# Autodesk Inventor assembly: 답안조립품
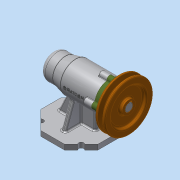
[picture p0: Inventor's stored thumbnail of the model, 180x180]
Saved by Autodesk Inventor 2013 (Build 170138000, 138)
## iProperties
Created: 2019-12
Part Number: 답안조립품
Document SubType Name: Assembly
Designer: Administrator
Author: Administrator
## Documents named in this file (12)
- C:\Users\Administrator\Desktop\491204V1026\답안조립품.iam
- C:\Users\Administrator\Desktop\491204V1026\본체.ipt
- C:\Users\Administrator\Desktop\491204V1026\커버.ipt
- C:\Users\Administrator\Desktop\491204V1026\축.ipt
- C:\Users\Administrator\Desktop\491204V1026\베어링 51202.ipt
- C:\Users\Administrator\Desktop\491204V1026\어댑터슬리브.ipt
- C:\Users\Administrator\Desktop\491204V1026\베어링 6004.ipt
- C:\Users\Administrator\Desktop\491204V1026\오일 실.ipt
- C:\Users\Administrator\Desktop\491204V1026\키 5 x 5 x 16.ipt
- C:\Users\Administrator\Desktop\491204V1026\V벨트풀리.ipt
- C:\Users\Administrator\Desktop\491204V1026\멈춤나사 M3.ipt
- C:\Users\Administrator\Desktop\491204V1026\볼트 M4.ipt
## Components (1 placed, 1 different names)
1. V벨트풀리:1
